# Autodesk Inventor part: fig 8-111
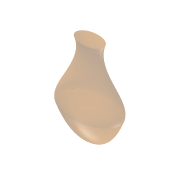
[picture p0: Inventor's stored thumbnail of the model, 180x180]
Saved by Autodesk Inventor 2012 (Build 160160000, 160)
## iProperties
Created: 2004-05
Part Number: fig 8-111
Document SubType Name: Modeling
Designer: CADCIM Technologies
Manufacturer: Standard
Standards Organization: Custom
Density: 1 g/cm^3
Material: Default
Author: CADCIM Technologies
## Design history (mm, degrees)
sketch "Sketch4"
  geometry: 1 further point; 1 other entity
  constraints: 2 other
workplane "Work Plane2"
sketch "Sketch5"
  geometry: 1 further point; 1 other entity
  constraints: 2 other
feature "LoftSrf1" sketch "Sketch5" dims "d4" = 20, "d5" = 110 deg, "d6" = 40, "d7" = 70 deg
patch "Boundary Patch2" dims "d10" = 0, "d11" = 0
patch "Boundary Patch3" dims "d13" = 0, "d14" = 0
body "Srf1"
body "Srf3"
body "Srf4"
other parameters: "d3" = 33.5
